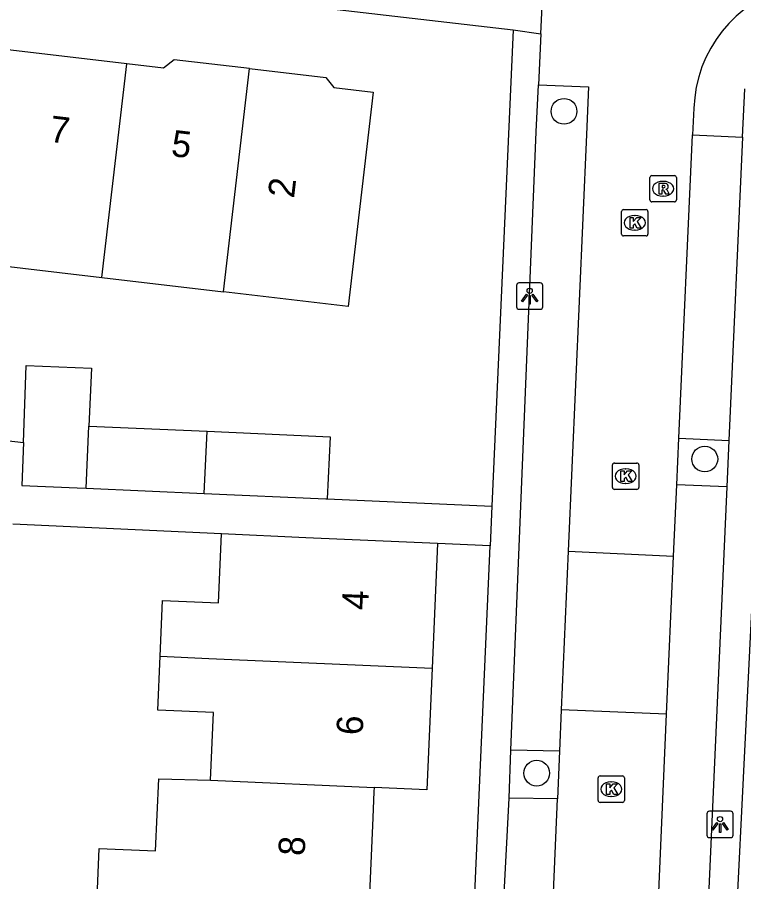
# Model space of a CAD drawing. Extents: x 162250 to 162654, y 380744 to 381605.
# Drawn here: x 162322.76 to 162350.32, y 381081.68 to 381114.47 of the extents above; entities that cross this region are included whole.
import ezdxf

# ---------------------------------------------------------------- set-up
doc = ezdxf.new("R2010")
doc.units = 0
for name, color, linetype in [('IMGEO_Boom', 7, 'Continuous'), ('IMGEO_Kolk', 7, 'Continuous'), ('IMGEO_Lichtpunt', 7, 'Continuous'), ('IMGEO_Pand', 7, 'Continuous'), ('IMGEO_Pand_nummerreeks', 7, 'Continuous'), ('IMGEO_Parkeervlak_open', 7, 'Continuous'), ('IMGEO_Rijbaan_lokaal_open', 7, 'Continuous'), ('IMGEO_Rioolput', 7, 'Continuous'), ('IMGEO_Voetpad_open', 7, 'Continuous')]:
    doc.layers.add(name, color=color, linetype=linetype)

msp = doc.modelspace()

# ---------------------------------------------------------------- linework, layer by layer
at = {"layer": 'IMGEO_Boom'}
for centre in [(162343.5, 381110.9), (162348.84, 381097.711), (162342.464, 381085.796)]:
    msp.add_circle(centre, 0.489, dxfattribs=at)
at = {"layer": 'IMGEO_Kolk'}
for p, q in [((162345.684, 381106.246), (162345.684, 381107.098)), ((162345.759, 381107.172), (162346.611, 381107.172)), ((162346.172, 381106.952), (162346.197, 381106.952)), ((162346.685, 381107.098), (162346.685, 381106.246)), ((162346.195, 381106.392), (162346.17, 381106.392)), ((162346.611, 381106.172), (162345.759, 381106.172)), ((162345.338, 381096.634), (162345.338, 381097.486)), ((162345.413, 381097.56), (162346.265, 381097.56)), ((162346.339, 381097.486), (162346.339, 381096.634)), ((162345.826, 381097.34), (162345.851, 381097.34)), ((162345.849, 381096.78), (162345.824, 381096.78)), ((162346.265, 381096.56), (162345.413, 381096.56)), ((162344.868, 381085.687), (162345.72, 381085.687)), ((162344.793, 381084.761), (162344.793, 381085.613)), ((162345.281, 381085.467), (162345.306, 381085.467)), ((162345.794, 381085.613), (162345.794, 381084.761)), ((162345.72, 381084.687), (162344.868, 381084.687)), ((162345.304, 381084.907), (162345.279, 381084.907))]:
    msp.add_line(p, q, dxfattribs=at)
for points in [[(162345.684, 381106.246), (162345.684, 381107.098)], [(162345.759, 381107.172), (162346.611, 381107.172)], [(162346.685, 381107.098), (162346.685, 381106.246)], [(162346.005, 381106.872), (162346.128, 381106.872), (162346.128, 381106.721), (162346.258, 381106.872), (162346.422, 381106.872), (162346.276, 381106.721), (162346.429, 381106.472), (162346.277, 381106.472), (162346.192, 381106.636), (162346.128, 381106.569), (162346.128, 381106.472), (162346.005, 381106.472), (162346.005, 381106.872)], [(162346.611, 381106.172), (162345.759, 381106.172)], [(162345.338, 381096.634), (162345.338, 381097.486)], [(162345.413, 381097.56), (162346.265, 381097.56)], [(162346.339, 381097.486), (162346.339, 381096.634)], [(162345.659, 381097.26), (162345.782, 381097.26), (162345.782, 381097.109), (162345.912, 381097.26), (162346.076, 381097.26), (162345.93, 381097.109), (162346.083, 381096.86), (162345.931, 381096.86), (162345.846, 381097.024), (162345.782, 381096.957), (162345.782, 381096.86), (162345.659, 381096.86), (162345.659, 381097.26)], [(162346.265, 381096.56), (162345.413, 381096.56)], [(162344.868, 381085.687), (162345.72, 381085.687)], [(162344.793, 381084.761), (162344.793, 381085.613)], [(162345.114, 381085.387), (162345.237, 381085.387), (162345.237, 381085.236), (162345.367, 381085.387), (162345.531, 381085.387), (162345.385, 381085.236), (162345.538, 381084.987), (162345.386, 381084.987), (162345.301, 381085.151), (162345.237, 381085.084), (162345.237, 381084.987), (162345.114, 381084.987), (162345.114, 381085.387)], [(162345.794, 381085.613), (162345.794, 381084.761)], [(162345.72, 381084.687), (162344.868, 381084.687)]]:
    msp.add_lwpolyline(points, dxfattribs=at)
for centre, start, end in [((162345.761, 381107.096), 91.552, 178.448), ((162345.761, 381107.096), 91.552, 178.448), ((162346.609, 381107.096), 1.552, 88.448), ((162346.609, 381107.096), 1.552, 88.448), ((162345.761, 381106.248), 181.552, 268.448), ((162345.761, 381106.248), 181.552, 268.448), ((162346.609, 381106.248), 271.552, 358.448), ((162346.609, 381106.248), 271.552, 358.448), ((162345.415, 381097.484), 91.552, 178.448), ((162345.415, 381097.484), 91.552, 178.448), ((162346.263, 381097.484), 1.552, 88.448), ((162346.263, 381097.484), 1.552, 88.448), ((162345.415, 381096.636), 181.552, 268.448), ((162345.415, 381096.636), 181.552, 268.448), ((162346.263, 381096.636), 271.552, 358.448), ((162346.263, 381096.636), 271.552, 358.448), ((162344.87, 381085.611), 91.552, 178.448), ((162344.87, 381085.611), 91.552, 178.448), ((162345.718, 381085.611), 1.552, 88.448), ((162345.718, 381085.611), 1.552, 88.448), ((162344.87, 381084.763), 181.552, 268.448), ((162344.87, 381084.763), 181.552, 268.448), ((162345.718, 381084.763), 271.552, 358.448), ((162345.718, 381084.763), 271.552, 358.448)]:
    msp.add_arc(centre, 0.0765, start, end, dxfattribs=at)
for centre, major_axis, ratio, start_param, end_param in [((162346.171, 381106.672), (-0.387, 0.002), 0.722429, 4.712389, 7.853982), ((162346.196, 381106.672), (-0.39, 0.002), 0.717154, 1.570796, 4.712389), ((162345.825, 381097.06), (-0.387, 0.002), 0.722429, 4.712389, 7.853982), ((162345.85, 381097.06), (-0.39, 0.002), 0.717154, 1.570796, 4.712389), ((162345.28, 381085.187), (-0.387, 0.002), 0.722429, 4.712389, 7.853982), ((162345.305, 381085.187), (-0.39, 0.002), 0.717154, 1.570796, 4.712389)]:
    msp.add_ellipse(centre, major_axis=major_axis, ratio=ratio, start_param=start_param, end_param=end_param, dxfattribs=at)
at = {"layer": 'IMGEO_Lichtpunt'}
for p, q in [((162342.6, 381104.391), (162341.792, 381104.391)), ((162342.6, 381104.391), (162341.792, 381104.391)), ((162341.698, 381104.296), (162341.698, 381103.489)), ((162341.698, 381104.296), (162341.698, 381103.489)), ((162342.694, 381103.489), (162342.694, 381104.296)), ((162342.694, 381103.489), (162342.694, 381104.296)), ((162341.792, 381103.395), (162342.6, 381103.395)), ((162341.792, 381103.395), (162342.6, 381103.395)), ((162349.822, 381084.349), (162349.014, 381084.349)), ((162349.822, 381084.349), (162349.014, 381084.349)), ((162348.92, 381084.254), (162348.92, 381083.447)), ((162348.92, 381084.254), (162348.92, 381083.447)), ((162349.916, 381083.447), (162349.916, 381084.254)), ((162349.916, 381083.447), (162349.916, 381084.254)), ((162349.014, 381083.353), (162349.822, 381083.353)), ((162349.014, 381083.353), (162349.822, 381083.353))]:
    msp.add_line(p, q, dxfattribs=at)
for points in [[(162342.072, 381103.96), (162342.111, 381103.932), (162341.923, 381103.67), (162341.885, 381103.697), (162342.072, 381103.96)], [(162342.174, 381103.912), (162342.221, 381103.912), (162342.221, 381103.59), (162342.174, 381103.59), (162342.174, 381103.912)], [(162342.284, 381103.932), (162342.322, 381103.959), (162342.509, 381103.697), (162342.47, 381103.669), (162342.284, 381103.932)], [(162349.294, 381083.918), (162349.333, 381083.89), (162349.145, 381083.628), (162349.107, 381083.655), (162349.294, 381083.918)], [(162349.396, 381083.87), (162349.443, 381083.87), (162349.443, 381083.548), (162349.396, 381083.548), (162349.396, 381083.87)], [(162349.506, 381083.89), (162349.544, 381083.917), (162349.731, 381083.655), (162349.692, 381083.627), (162349.506, 381083.89)]]:
    msp.add_lwpolyline(points, dxfattribs=at)
for centre in [(162342.197, 381104.094), (162349.419, 381084.052)]:
    msp.add_circle(centre, 0.0994, dxfattribs=at)
for centre, start, end in [((162341.792, 381104.296), 90, 180), ((162341.792, 381104.296), 90, 180), ((162342.6, 381104.296), 0, 90), ((162342.6, 381104.296), 0, 90), ((162341.792, 381103.489), 180, 270), ((162341.792, 381103.489), 180, 270), ((162342.6, 381103.489), 270, 0), ((162342.6, 381103.489), 270, 360), ((162349.014, 381084.254), 90, 180), ((162349.014, 381084.254), 90, 180), ((162349.822, 381084.254), 0, 90), ((162349.822, 381084.254), 0, 90), ((162349.014, 381083.447), 180, 270), ((162349.014, 381083.447), 180, 270), ((162349.822, 381083.447), 270, 0), ((162349.822, 381083.447), 270, 360)]:
    msp.add_arc(centre, 0.0946, start, end, dxfattribs=at)
at = {"layer": 'IMGEO_Pand'}
for points in [[(162326.914, 381112.705), (162322.299, 381113.246)], [(162331.571, 381112.519), (162328.707, 381112.855), (162328.309, 381112.541), (162326.914, 381112.705)], [(162325.963, 381104.596), (162326.914, 381112.705)], [(162330.578, 381104.055), (162331.571, 381112.519)], [(162331.571, 381112.519), (162334.469, 381112.179), (162334.767, 381111.802), (162336.266, 381111.626), (162335.313, 381103.499), (162330.578, 381104.055)], [(162321.348, 381105.137), (162325.963, 381104.596)], [(162325.963, 381104.596), (162330.578, 381104.055)], [(162322.993, 381098.336), (162323.098, 381101.264), (162325.575, 381101.155), (162325.478, 381098.962)], [(162325.374, 381096.6), (162325.478, 381098.962)], [(162325.478, 381098.962), (162329.957, 381098.765)], [(162329.853, 381096.402), (162329.957, 381098.765)], [(162329.957, 381098.765), (162334.625, 381098.559), (162334.521, 381096.197)], [(162322.993, 381098.336), (162322.934, 381096.707), (162325.027, 381096.615), (162325.374, 381096.6)], [(162325.374, 381096.6), (162329.853, 381096.402)], [(162329.853, 381096.402), (162334.463, 381096.199), (162334.521, 381096.197)], [(162328.181, 381090.229), (162328.274, 381092.345), (162330.388, 381092.252), (162330.503, 381094.867)], [(162338.705, 381094.506), (162333.71, 381094.726), (162330.503, 381094.867)], [(162338.705, 381094.506), (162338.497, 381089.775)], [(162330.088, 381085.526), (162330.201, 381088.097), (162328.092, 381088.19), (162328.181, 381090.229)], [(162328.181, 381090.229), (162330.02, 381090.148), (162338.497, 381089.775)], [(162338.497, 381089.775), (162338.294, 381085.165), (162336.297, 381085.253)], [(162327.869, 381081.005), (162327.721, 381081.011), (162325.787, 381081.096), (162325.868, 381082.941), (162328.005, 381082.846), (162328.125, 381085.575), (162330.088, 381085.526)], [(162330.088, 381085.526), (162336.297, 381085.253)], [(162336.297, 381085.253), (162336.29, 381085.1), (162336.246, 381084.098), (162336.094, 381080.643)]]:
    msp.add_lwpolyline(points, dxfattribs=at)
at = {"layer": 'IMGEO_Parkeervlak_open'}
for points in [[(162348.369, 381110.012), (162350.27, 381109.922)], [(162347.851, 381098.505), (162349.753, 381098.417)], [(162349.681, 381096.654), (162347.782, 381096.729)], [(162343.329, 381086.625), (162341.485, 381086.666)], [(162343.253, 381084.815), (162341.423, 381084.846)]]:
    msp.add_lwpolyline(points, dxfattribs=at)
at = {"layer": 'IMGEO_Rijbaan_lokaal_open'}
for points in [[(162342.62, 381113.844), (162342.693, 381115.454)], [(162342.62, 381113.844), (162342.532, 381111.902)], [(162342.532, 381111.902), (162344.432, 381111.824), (162344.356, 381110.027), (162343.656, 381094.218)], [(162348.429, 381111.017), (162348.369, 381110.012)], [(162347.851, 381098.505), (162348.369, 381110.012)], [(162347.782, 381096.729), (162347.851, 381098.505)], [(162347.658, 381094.025), (162347.782, 381096.729)], [(162343.656, 381094.218), (162343.397, 381088.199)], [(162343.656, 381094.218), (162347.658, 381094.025)], [(162347.384, 381088.031), (162347.658, 381094.025)], [(162343.397, 381088.199), (162343.329, 381086.625)], [(162347.384, 381088.031), (162343.397, 381088.199)], [(162346.706, 381072.194), (162347.384, 381088.031)], [(162343.329, 381086.625), (162343.253, 381084.815)], [(162342.292, 381062.308), (162343.253, 381084.815)]]:
    msp.add_lwpolyline(points, dxfattribs=at)
msp.add_arc((162353.307, 381110.888), 4.879, 104.0271, 178.4866, dxfattribs=at)
at = {"layer": 'IMGEO_Rioolput'}
for p, q in [((162346.76, 381107.539), (162346.76, 381108.391)), ((162346.835, 381108.465), (162347.687, 381108.465)), ((162347.248, 381108.245), (162347.273, 381108.245)), ((162347.761, 381108.391), (162347.761, 381107.539)), ((162347.271, 381107.685), (162347.246, 381107.685)), ((162347.687, 381107.465), (162346.835, 381107.465))]:
    msp.add_line(p, q, dxfattribs=at)
for points in [[(162346.76, 381107.539), (162346.76, 381108.391)], [(162346.835, 381108.465), (162347.687, 381108.465)], [(162347.761, 381108.391), (162347.761, 381107.539)], [(162347.349, 381108.163), (162347.097, 381108.165), (162347.097, 381107.765)], [(162347.097, 381107.765), (162347.221, 381107.765), (162347.221, 381107.927), (162347.232, 381107.927)], [(162347.275, 381108.084), (162347.221, 381108.084), (162347.221, 381108.003)], [(162347.221, 381108.003), (162347.273, 381108.003)], [(162347.279, 381107.898), (162347.35, 381107.765), (162347.49, 381107.765), (162347.425, 381107.891)], [(162347.687, 381107.465), (162346.835, 381107.465)]]:
    msp.add_lwpolyline(points, dxfattribs=at)
for centre, radius, start, end in [((162346.837, 381108.389), 0.0765, 91.552, 178.448), ((162346.837, 381108.389), 0.0765, 91.552, 178.448), ((162347.685, 381108.389), 0.0765, 1.552, 88.448), ((162347.685, 381108.389), 0.0765, 1.552, 88.448), ((162347.231, 381107.874), 0.0533, 26.0293, 88.6989), ((162347.257, 381108.192), 0.19, 274.7715, 282.9687), ((162347.281, 381107.988), 0.0964, 77.0061, 93.1865), ((162347.295, 381108.045), 0.0378, 276.6634, 79.6772), ((162347.348, 381108.053), 0.109, 350.3612, 89.416), ((162347.346, 381108.053), 0.112, 277.5842, 350.9817), ((162347.33, 381107.838), 0.108, 29.5134, 73.7905), ((162346.837, 381107.541), 0.0765, 181.552, 268.448), ((162346.837, 381107.541), 0.0765, 181.552, 268.448), ((162347.685, 381107.541), 0.0765, 271.552, 358.448), ((162347.685, 381107.541), 0.0765, 271.552, 358.448)]:
    msp.add_arc(centre, radius, start, end, dxfattribs=at)
for centre, major_axis, ratio, start_param, end_param in [((162347.247, 381107.965), (-0.387, 0.002), 0.722429, 4.712389, 7.853982), ((162347.272, 381107.965), (-0.39, 0.002), 0.717154, 1.570796, 4.712389)]:
    msp.add_ellipse(centre, major_axis=major_axis, ratio=ratio, start_param=start_param, end_param=end_param, dxfattribs=at)
at = {"layer": 'IMGEO_Voetpad_open'}
for points in [[(162300.19, 381118.786), (162341.565, 381113.994)], [(162341.565, 381113.994), (162340.767, 381095.921)], [(162341.565, 381113.994), (162342.62, 381113.844)], [(162341.485, 381086.666), (162342.447, 381110.128), (162342.532, 381111.902)], [(162350.27, 381109.922), (162350.364, 381111.754)], [(162350.27, 381109.922), (162349.753, 381098.417)], [(162320.583, 381098.618), (162322.993, 381098.336)], [(162349.753, 381098.417), (162349.681, 381096.654)], [(162349.681, 381096.654), (162348.578, 381072.082)], [(162334.521, 381096.197), (162340.767, 381095.921)], [(162340.767, 381095.921), (162340.701, 381094.418)], [(162330.503, 381094.867), (162322.586, 381095.235)], [(162340.701, 381094.418), (162338.705, 381094.506)], [(162336.141, 380988.151), (162336.6, 381000), (162337.62, 381024.184), (162335.584, 381024.354), (162336.016, 381034.263), (162338.044, 381034.203), (162340.701, 381094.418)], [(162350.659, 381092.985), (162349.693, 381073.414), (162350.924, 381073.314), (162350.066, 381051.483), (162348.851, 381051.523), (162346.572, 381000), (162346.066, 380986.918)], [(162341.423, 381084.846), (162341.485, 381086.666)], [(162340.374, 381062.382), (162340.838, 381073.728), (162341.423, 381084.846)]]:
    msp.add_lwpolyline(points, dxfattribs=at)

# ---------------------------------------------------------------- texts
at = {"layer": 'IMGEO_Pand_nummerreeks'}
for s, rotation, p in [('7', 353.3088, (162323.951, 381109.749)), ('5', 353.3088, (162328.566, 381109.208)), ('2', 83.3118, (162333.255, 381107.58)), ('4', 87.479, (162336.071, 381091.969)), ('6', 87.4792, (162335.862, 381087.222)), ('8', 87.4792, (162333.66, 381082.643))]:
    msp.add_text(s, height=1, rotation=rotation, dxfattribs=at).set_placement(p)

doc.saveas('drawing.dxf')
